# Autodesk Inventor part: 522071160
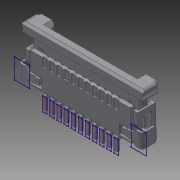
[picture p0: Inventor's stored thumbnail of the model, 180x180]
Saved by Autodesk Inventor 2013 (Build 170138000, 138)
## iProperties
Created: 2012-08
Part Number: 522071160
Material: Allgemein
Document SubType Name: Modeling
Designer: rYan
Categories: <MemberInstance><Categories><Category DisplayName="" Mnemonic="CABLEANDHARNESS" InternalName="e4a7e005-5e42-4d16-b293-125e7f0d0512"><Category DisplayName="" Mne
Density: 1 g/cm^3
Mass: 0.182449 g
Surface Area: 8.62074 cm^2
Volume: 0.182449 cm^3
Übersetzungsnorm: STEP AP203
Dateiname: 522071160
Vorprozessor: PRO/ENGINEER BY PARAMETRIC TECHNOLOGY CORPORATION, 2003451
Postprozessor: Build: 138, Release: 2013 RTM - Date: Thu 03/01/2012
Gesendete Einheiten: Millimeter
Unbestimmtheit: 0.002074742300838
Author: rYan
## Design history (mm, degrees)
node "5220711601"
  sketch "3D-Skizze1"
workpoint "Arbeitspunkt1"
node "1"
node "2"
node "3"
node "4"
node "5"
node "6"
node "7"
node "8"
node "9"
node "10"
node "11"
node "522071160"
node "522071160_1"
node "522071160_2"
node "Basis1"
node "Basis2"
node "Basis3"
